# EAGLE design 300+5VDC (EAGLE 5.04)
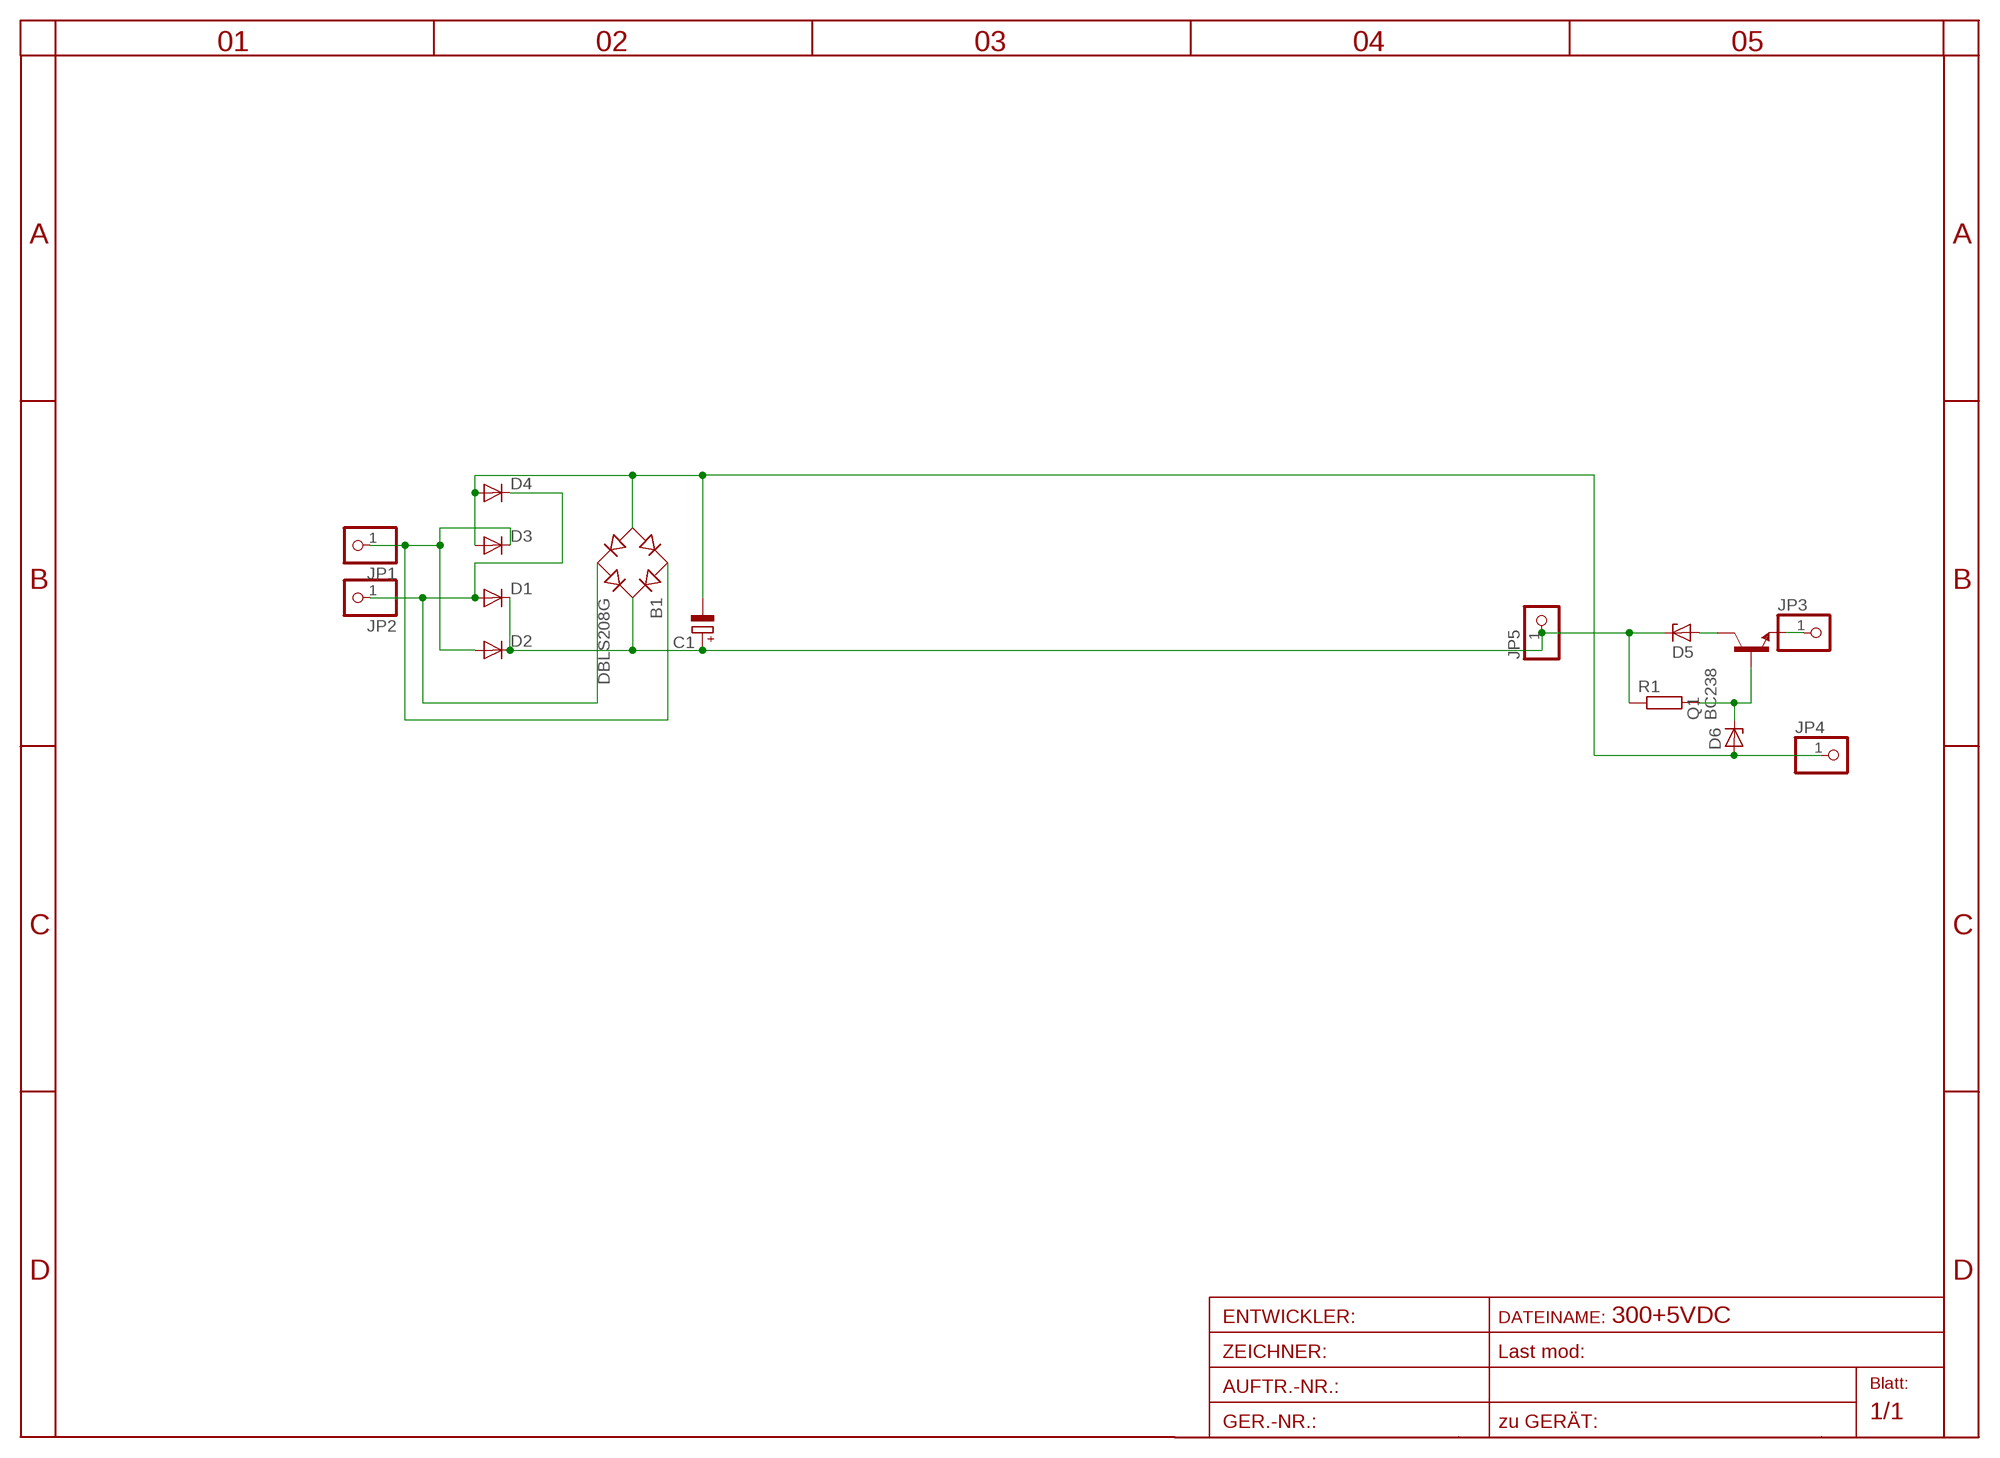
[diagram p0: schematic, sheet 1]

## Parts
B1  DBLS208G  [DBS]
C1  CPOL-EUE5-8.5  [E5-8,5]
D1  DIODE-DO35-10  [DO35-10]
D2  DIODE-D-5  [D-5]
D3  DIODE-DO35-10  [DO35-10]
D4  DIODE-D-5  [D-5]
D5  ZENER-DIODEZD-10  [ZDIO-10]
D6  ZENER-DIODEZD-5  [ZDIO-5]
JP1  PINHD-1X1  [1X01]
JP2  PINHD-1X1  [1X01]
JP3  PINHD-1X1  [1X01]
JP4  PINHD-1X1  [1X01]
JP5  PINHD-1X1  [1X01]
Q1  BC238  [TO92]
R1  R-EU_0207/12  [0207/12]

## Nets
N$1: B1.- C1.- D3.A D4.A D6.A JP4.1
N$2: B1.+ C1.+ D1.C D2.C D5.C JP5.1 R1.1
N$3: B1.AC1 D2.A D3.C JP1.1
N$4: B1.AC2 D1.A D4.C JP2.1
N$5: D6.C Q1.2(B) R1.2
N$6: D5.A Q1.3(C)
N$7: JP3.1 Q1.1(E)

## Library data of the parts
B1 = rectifier:DB?*G: Single Phase 1.0 AMP Glass Passivated Bridge Rectifier Taiwan Semiconductor Co.,Ltd. - TSC Source: http://www.taiwansemi.com/TSCbig5/ezcatfiles/cust/img/img/db101g.pdf http://www.ts.com.tw/db/pictures/modules/PDT/PDT060207001/DBLS201G.pdf
C1 = rcl-2:CPOL-EU: POLARIZED CAPACITOR, European symbol
D1-D4 = diode-1:DIODE-: DIODE
D5 D6 = diode-1:ZENER-DIODE: Z-Diode
JP1-JP5 = pinhead:PINHD-1X1: PIN HEADER
Q1 = transistor-npn:BC238: NPN Transistor
R1 = rcl-2:R-EU_: RESISTOR, European symbol

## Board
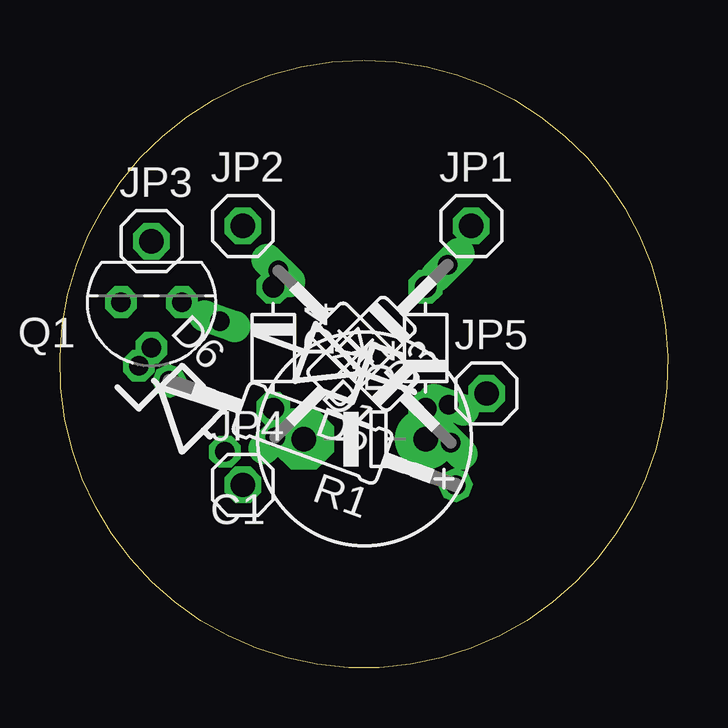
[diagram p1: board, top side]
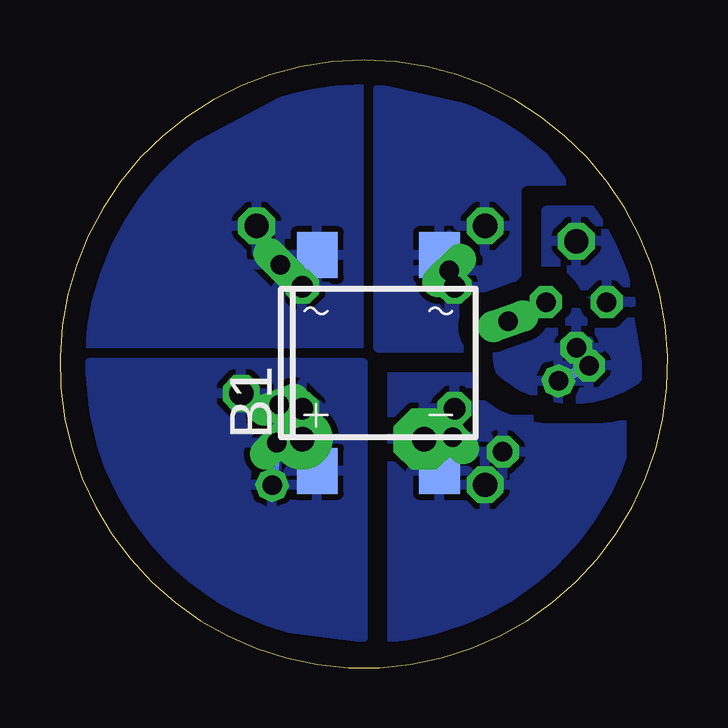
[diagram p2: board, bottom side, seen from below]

Size 25.35 x 25.34 mm. Coordinates in mm from the lower left corner, seen from the top.
Outline: 12.7,25.34 arc-360 12.64,25.34
Copper layers (1*16): Top 0.035mm / dielectric 1.5mm / Bottom 0.035mm
Design rules "default": minimum track width 10mil, minimum drill 24mil, track to track 8mil, track to pad 8mil, pad to pad 8mil, via to via 8mil, smd to smd 8mil, copper to edge 40mil, drill to drill 8mil, minimum pad ring 10mil, minimum via ring 8mil, stop-mask expansion 4mil, vias tented up to drill 0mil, thermal gap 10mil

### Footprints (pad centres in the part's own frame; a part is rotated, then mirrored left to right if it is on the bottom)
DBS = smd 1.7 x 1.9: + -2.55,-4.5; - 2.55,-4.5; AC1 -2.55,4.5; AC2 2.55,4.5
E5-8,5 = drill 1.016 pad 2.54 round: + -2.54,0 | drill 1.016 pad 2.54 octagon: - 2.54,0
DO35-10 = drill 0.813 long: A 5.08,0; C -5.08,0
D-5 = drill 0.9 octagon: A 2.54,0; C -2.54,0
ZDIO-10 = drill 0.813 long: A 5.08,0; C -5.08,0
ZDIO-5 = drill 0.813 octagon: A 2.54,0; C -2.54,0
1X01 = drill 1.016 octagon: 1 0,0
TO92 = drill 0.813 octagon: 1 1.27,0; 2 0,1.905; 3 -1.27,0
0207/12 = drill 0.813 octagon: 1 -6.35,0; 2 6.35,0

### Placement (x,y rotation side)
B1  12.07,12.7 0 bottom
C1  12.7,9.53 180 top
D1  12.7,12.96 135 top
D2  15.24,13.34 90 top
D3  12.57,13.2 225 top
D4  8.89,13.34 270 top
D5  11.43,12.7 160 top
D6  5.08,10.8 315 top
JP1  17.15,18.42 0 top
JP2  7.62,18.42 0 top
JP3  3.81,17.78 0 top
JP4  7.62,7.62 0 top
JP5  17.78,11.43 0 top
Q1  3.81,15.24 180 top
R1  10.53,9.78 160 top

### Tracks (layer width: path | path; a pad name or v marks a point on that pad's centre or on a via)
N$1
  Bottom 0.406: C1.- D3.A D4.A
  pour Bottom (isolate 0.813, rank 4): 1.91,12.7 12.7,12.7 12.7,0.64 6.99,1.91 1.91,6.99
N$2
  Bottom 0.406: R1.1 D1.C C1.+ | D5.C D2.C
  pour Bottom (isolate 0.813, rank 2): 12.7,12.7 24.13,12.7 23.5,6.35 17.78,1.91 12.7,1.27
N$3
  pour Bottom (isolate 0.406, rank 3): 12.7,25.4 12.7,12.7 24.77,13.34 23.5,19.69
N$4
  Bottom 0.406: D4.C D1.A
  pour Bottom (isolate 0.813, rank 2): 6.35,22.86 2.54,17.78 1.27,13.34 12.07,13.34 12.07,24.13
N$5
  Bottom 0.406: Q1.2 D6.C R1.2
  pour Bottom (isolate 0.406, rank 3): 1.27,12.07 1.27,12.7 1.91,16.51 3.5,15.88 arc-127 6.99,12.38 arc-78
N$6
  Bottom 0.406: D5.A Q1.3
N$7
  pour Bottom (isolate 0.813): 2.54,15.24 1.27,15.24 2.54,19.05 5.08,19.05 5.08,16.51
